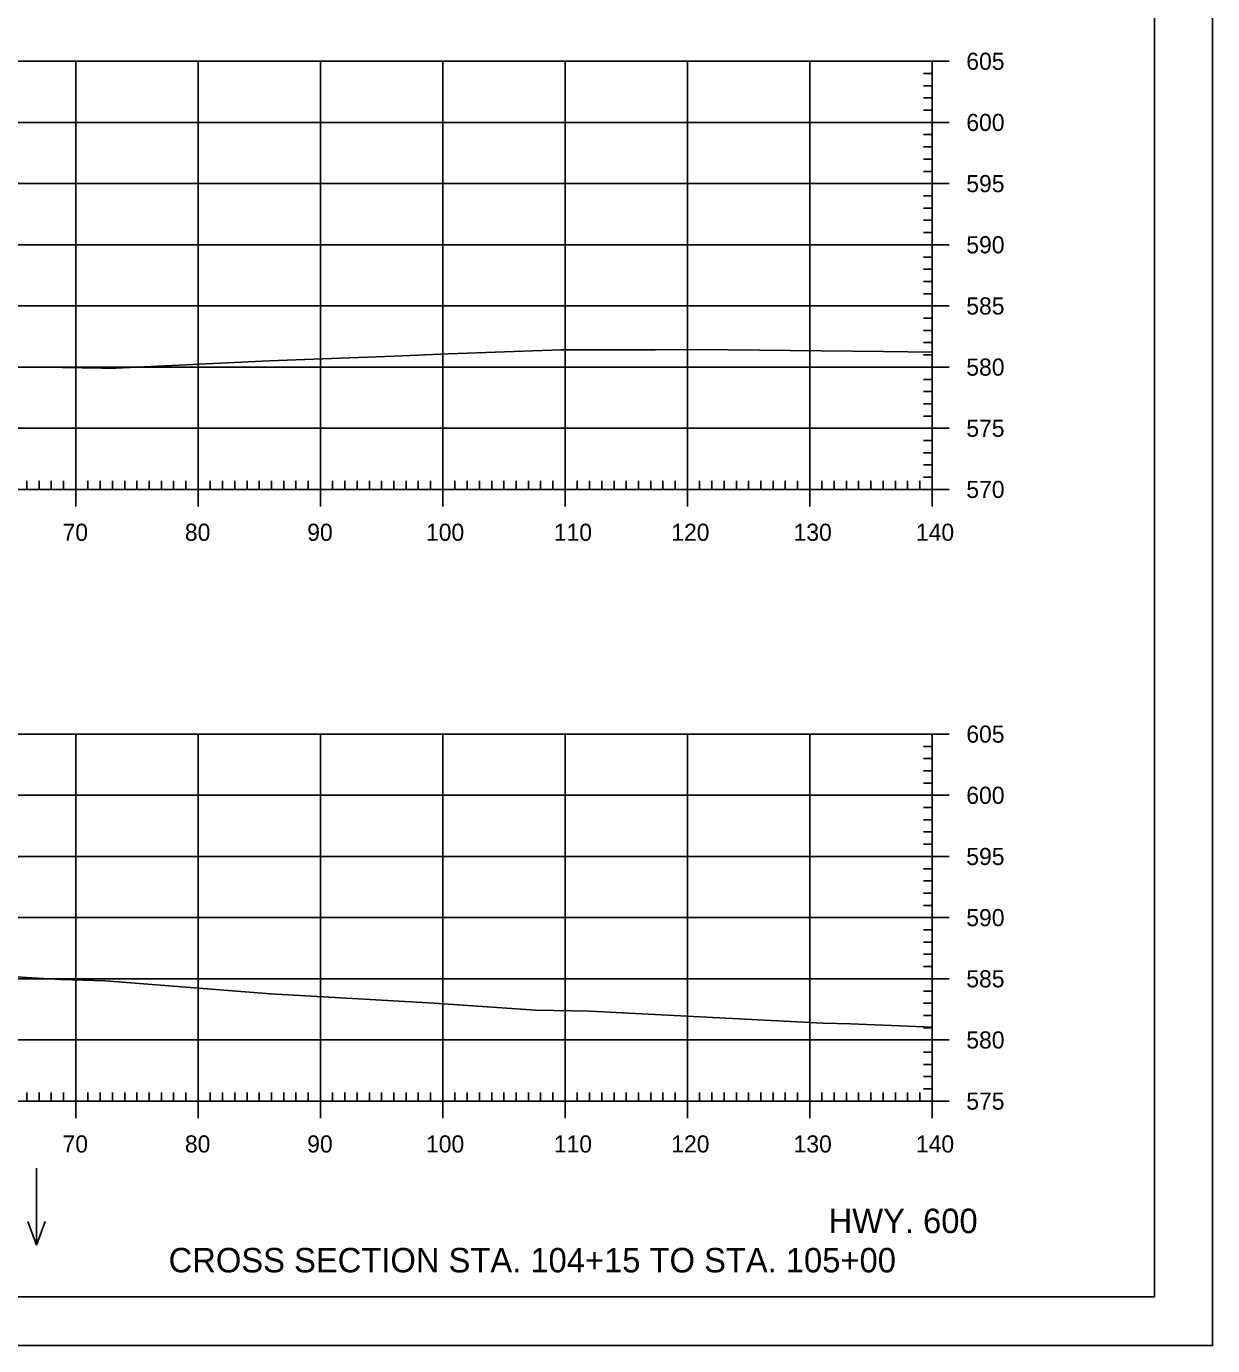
# Model space of a CAD drawing. Extents: x 961436 to 1372525, y 380079 to 2027791.
# Drawn here: x 1370699.8 to 1370796.7, y 380322.4 to 380430.3 of the extents above; entities that cross this region are included whole.
import ezdxf

# ---------------------------------------------------------------- set-up
doc = ezdxf.new("R2010")
doc.units = 0
for name, color, linetype in [('R_Axis', 7, 'Continuous'), ('R_Axis Annot', 7, 'Continuous'), ('R_Draft', 7, 'Continuous'), ('R_Exist Surface', 7, 'Continuous'), ('R_Grid', 7, 'Continuous'), ('R_No Plot', 7, 'Continuous'), ('R_Water Annot', 7, 'Continuous')]:
    doc.layers.add(name, color=color, linetype=linetype)

msp = doc.modelspace()

# ---------------------------------------------------------------- linework, layer by layer
at = {"layer": 'R_Axis'}
for p, q in [((1370775.21, 380427.4), (1370772.41, 380427.4)), ((1370773.81, 380392.4), (1370773.81, 380427.4)), ((1370773.81, 380426.4), (1370773.11, 380426.4)), ((1370773.81, 380425.4), (1370773.11, 380425.4)), ((1370773.81, 380424.4), (1370773.11, 380424.4)), ((1370773.81, 380423.4), (1370773.11, 380423.4)), ((1370775.21, 380422.4), (1370772.41, 380422.4)), ((1370773.81, 380421.4), (1370773.11, 380421.4)), ((1370773.81, 380420.4), (1370773.11, 380420.4)), ((1370773.81, 380419.4), (1370773.11, 380419.4)), ((1370773.81, 380418.4), (1370773.11, 380418.4)), ((1370775.21, 380417.4), (1370772.41, 380417.4)), ((1370773.81, 380416.4), (1370773.11, 380416.4)), ((1370773.81, 380415.4), (1370773.11, 380415.4)), ((1370773.81, 380414.4), (1370773.11, 380414.4)), ((1370773.81, 380413.4), (1370773.11, 380413.4)), ((1370775.21, 380412.4), (1370772.41, 380412.4)), ((1370773.81, 380411.4), (1370773.11, 380411.4)), ((1370773.81, 380410.4), (1370773.11, 380410.4)), ((1370773.81, 380409.4), (1370773.11, 380409.4)), ((1370773.81, 380408.4), (1370773.11, 380408.4)), ((1370775.21, 380407.4), (1370772.41, 380407.4)), ((1370773.81, 380406.4), (1370773.11, 380406.4)), ((1370773.81, 380405.4), (1370773.11, 380405.4)), ((1370773.81, 380404.4), (1370773.11, 380404.4)), ((1370773.81, 380403.4), (1370773.11, 380403.4)), ((1370775.21, 380402.4), (1370772.41, 380402.4)), ((1370773.81, 380401.4), (1370773.11, 380401.4)), ((1370773.81, 380400.4), (1370773.11, 380400.4)), ((1370773.81, 380399.4), (1370773.11, 380399.4)), ((1370773.81, 380398.4), (1370773.11, 380398.4)), ((1370775.21, 380397.4), (1370772.41, 380397.4)), ((1370773.81, 380396.4), (1370773.11, 380396.4)), ((1370773.81, 380395.4), (1370773.11, 380395.4)), ((1370703.81, 380391), (1370703.81, 380393.8)), ((1370713.81, 380391), (1370713.81, 380393.8)), ((1370723.81, 380391), (1370723.81, 380393.8)), ((1370733.81, 380391), (1370733.81, 380393.8)), ((1370743.81, 380391), (1370743.81, 380393.8)), ((1370753.81, 380391), (1370753.81, 380393.8)), ((1370763.81, 380391), (1370763.81, 380393.8)), ((1370773.81, 380394.4), (1370773.11, 380394.4)), ((1370773.81, 380391), (1370773.81, 380393.8)), ((1370699.81, 380392.4), (1370699.81, 380393.1)), ((1370700.81, 380392.4), (1370700.81, 380393.1)), ((1370701.81, 380392.4), (1370701.81, 380393.1)), ((1370702.81, 380392.4), (1370702.81, 380393.1)), ((1370704.81, 380392.4), (1370704.81, 380393.1)), ((1370705.81, 380392.4), (1370705.81, 380393.1)), ((1370706.81, 380392.4), (1370706.81, 380393.1)), ((1370707.81, 380392.4), (1370707.81, 380393.1)), ((1370708.81, 380392.4), (1370708.81, 380393.1)), ((1370709.81, 380392.4), (1370709.81, 380393.1)), ((1370710.81, 380392.4), (1370710.81, 380393.1)), ((1370711.81, 380392.4), (1370711.81, 380393.1)), ((1370712.81, 380392.4), (1370712.81, 380393.1)), ((1370714.81, 380392.4), (1370714.81, 380393.1)), ((1370715.81, 380392.4), (1370715.81, 380393.1)), ((1370716.81, 380392.4), (1370716.81, 380393.1)), ((1370717.81, 380392.4), (1370717.81, 380393.1)), ((1370718.81, 380392.4), (1370718.81, 380393.1)), ((1370719.81, 380392.4), (1370719.81, 380393.1)), ((1370720.81, 380392.4), (1370720.81, 380393.1)), ((1370721.81, 380392.4), (1370721.81, 380393.1)), ((1370722.81, 380392.4), (1370722.81, 380393.1)), ((1370724.81, 380392.4), (1370724.81, 380393.1)), ((1370725.81, 380392.4), (1370725.81, 380393.1)), ((1370726.81, 380392.4), (1370726.81, 380393.1)), ((1370727.81, 380392.4), (1370727.81, 380393.1)), ((1370728.81, 380392.4), (1370728.81, 380393.1)), ((1370729.81, 380392.4), (1370729.81, 380393.1)), ((1370730.81, 380392.4), (1370730.81, 380393.1)), ((1370731.81, 380392.4), (1370731.81, 380393.1)), ((1370732.81, 380392.4), (1370732.81, 380393.1)), ((1370734.81, 380392.4), (1370734.81, 380393.1)), ((1370735.81, 380392.4), (1370735.81, 380393.1)), ((1370736.81, 380392.4), (1370736.81, 380393.1)), ((1370737.81, 380392.4), (1370737.81, 380393.1)), ((1370738.81, 380392.4), (1370738.81, 380393.1)), ((1370739.81, 380392.4), (1370739.81, 380393.1)), ((1370740.81, 380392.4), (1370740.81, 380393.1)), ((1370741.81, 380392.4), (1370741.81, 380393.1)), ((1370742.81, 380392.4), (1370742.81, 380393.1)), ((1370744.81, 380392.4), (1370744.81, 380393.1)), ((1370745.81, 380392.4), (1370745.81, 380393.1)), ((1370746.81, 380392.4), (1370746.81, 380393.1)), ((1370747.81, 380392.4), (1370747.81, 380393.1)), ((1370748.81, 380392.4), (1370748.81, 380393.1)), ((1370749.81, 380392.4), (1370749.81, 380393.1)), ((1370750.81, 380392.4), (1370750.81, 380393.1)), ((1370751.81, 380392.4), (1370751.81, 380393.1)), ((1370752.81, 380392.4), (1370752.81, 380393.1)), ((1370754.81, 380392.4), (1370754.81, 380393.1)), ((1370755.81, 380392.4), (1370755.81, 380393.1)), ((1370756.81, 380392.4), (1370756.81, 380393.1)), ((1370757.81, 380392.4), (1370757.81, 380393.1)), ((1370758.81, 380392.4), (1370758.81, 380393.1)), ((1370759.81, 380392.4), (1370759.81, 380393.1)), ((1370760.81, 380392.4), (1370760.81, 380393.1)), ((1370761.81, 380392.4), (1370761.81, 380393.1)), ((1370762.81, 380392.4), (1370762.81, 380393.1)), ((1370764.81, 380392.4), (1370764.81, 380393.1)), ((1370765.81, 380392.4), (1370765.81, 380393.1)), ((1370766.81, 380392.4), (1370766.81, 380393.1)), ((1370767.81, 380392.4), (1370767.81, 380393.1)), ((1370768.81, 380392.4), (1370768.81, 380393.1)), ((1370769.81, 380392.4), (1370769.81, 380393.1)), ((1370770.81, 380392.4), (1370770.81, 380393.1)), ((1370771.81, 380392.4), (1370771.81, 380393.1)), ((1370772.81, 380392.4), (1370772.81, 380393.1)), ((1370773.81, 380393.4), (1370773.11, 380393.4)), ((1370493.81, 380392.4), (1370773.81, 380392.4)), ((1370775.21, 380392.4), (1370772.41, 380392.4)), ((1370775.21, 380372.4), (1370772.41, 380372.4)), ((1370773.81, 380342.4), (1370773.81, 380372.4)), ((1370773.81, 380371.4), (1370773.11, 380371.4)), ((1370773.81, 380370.4), (1370773.11, 380370.4)), ((1370773.81, 380369.4), (1370773.11, 380369.4)), ((1370773.81, 380368.4), (1370773.11, 380368.4)), ((1370775.21, 380367.4), (1370772.41, 380367.4)), ((1370773.81, 380366.4), (1370773.11, 380366.4)), ((1370773.81, 380365.4), (1370773.11, 380365.4)), ((1370773.81, 380364.4), (1370773.11, 380364.4)), ((1370773.81, 380363.4), (1370773.11, 380363.4)), ((1370775.21, 380362.4), (1370772.41, 380362.4)), ((1370773.81, 380361.4), (1370773.11, 380361.4)), ((1370773.81, 380360.4), (1370773.11, 380360.4)), ((1370773.81, 380359.4), (1370773.11, 380359.4)), ((1370773.81, 380358.4), (1370773.11, 380358.4)), ((1370775.21, 380357.4), (1370772.41, 380357.4)), ((1370773.81, 380356.4), (1370773.11, 380356.4)), ((1370773.81, 380355.4), (1370773.11, 380355.4)), ((1370773.81, 380354.4), (1370773.11, 380354.4)), ((1370773.81, 380353.4), (1370773.11, 380353.4)), ((1370775.21, 380352.4), (1370772.41, 380352.4)), ((1370773.81, 380351.4), (1370773.11, 380351.4)), ((1370773.81, 380350.4), (1370773.11, 380350.4)), ((1370773.81, 380349.4), (1370773.11, 380349.4)), ((1370773.81, 380348.4), (1370773.11, 380348.4)), ((1370775.21, 380347.4), (1370772.41, 380347.4)), ((1370773.81, 380346.4), (1370773.11, 380346.4)), ((1370773.81, 380345.4), (1370773.11, 380345.4)), ((1370773.81, 380344.4), (1370773.11, 380344.4)), ((1370699.81, 380342.4), (1370699.81, 380343.1)), ((1370700.81, 380342.4), (1370700.81, 380343.1)), ((1370701.81, 380342.4), (1370701.81, 380343.1)), ((1370702.81, 380342.4), (1370702.81, 380343.1)), ((1370703.81, 380341), (1370703.81, 380343.8)), ((1370704.81, 380342.4), (1370704.81, 380343.1)), ((1370705.81, 380342.4), (1370705.81, 380343.1)), ((1370706.81, 380342.4), (1370706.81, 380343.1)), ((1370707.81, 380342.4), (1370707.81, 380343.1)), ((1370708.81, 380342.4), (1370708.81, 380343.1)), ((1370709.81, 380342.4), (1370709.81, 380343.1)), ((1370710.81, 380342.4), (1370710.81, 380343.1)), ((1370711.81, 380342.4), (1370711.81, 380343.1)), ((1370712.81, 380342.4), (1370712.81, 380343.1)), ((1370713.81, 380341), (1370713.81, 380343.8)), ((1370714.81, 380342.4), (1370714.81, 380343.1)), ((1370715.81, 380342.4), (1370715.81, 380343.1)), ((1370716.81, 380342.4), (1370716.81, 380343.1)), ((1370717.81, 380342.4), (1370717.81, 380343.1)), ((1370718.81, 380342.4), (1370718.81, 380343.1)), ((1370719.81, 380342.4), (1370719.81, 380343.1)), ((1370720.81, 380342.4), (1370720.81, 380343.1)), ((1370721.81, 380342.4), (1370721.81, 380343.1)), ((1370722.81, 380342.4), (1370722.81, 380343.1)), ((1370723.81, 380341), (1370723.81, 380343.8)), ((1370724.81, 380342.4), (1370724.81, 380343.1)), ((1370725.81, 380342.4), (1370725.81, 380343.1)), ((1370726.81, 380342.4), (1370726.81, 380343.1)), ((1370727.81, 380342.4), (1370727.81, 380343.1)), ((1370728.81, 380342.4), (1370728.81, 380343.1)), ((1370729.81, 380342.4), (1370729.81, 380343.1)), ((1370730.81, 380342.4), (1370730.81, 380343.1)), ((1370731.81, 380342.4), (1370731.81, 380343.1)), ((1370732.81, 380342.4), (1370732.81, 380343.1)), ((1370733.81, 380341), (1370733.81, 380343.8)), ((1370734.81, 380342.4), (1370734.81, 380343.1)), ((1370735.81, 380342.4), (1370735.81, 380343.1)), ((1370736.81, 380342.4), (1370736.81, 380343.1)), ((1370737.81, 380342.4), (1370737.81, 380343.1)), ((1370738.81, 380342.4), (1370738.81, 380343.1)), ((1370739.81, 380342.4), (1370739.81, 380343.1)), ((1370740.81, 380342.4), (1370740.81, 380343.1)), ((1370741.81, 380342.4), (1370741.81, 380343.1)), ((1370742.81, 380342.4), (1370742.81, 380343.1)), ((1370743.81, 380341), (1370743.81, 380343.8)), ((1370744.81, 380342.4), (1370744.81, 380343.1)), ((1370745.81, 380342.4), (1370745.81, 380343.1)), ((1370746.81, 380342.4), (1370746.81, 380343.1)), ((1370747.81, 380342.4), (1370747.81, 380343.1)), ((1370748.81, 380342.4), (1370748.81, 380343.1)), ((1370749.81, 380342.4), (1370749.81, 380343.1)), ((1370750.81, 380342.4), (1370750.81, 380343.1)), ((1370751.81, 380342.4), (1370751.81, 380343.1)), ((1370752.81, 380342.4), (1370752.81, 380343.1)), ((1370753.81, 380341), (1370753.81, 380343.8)), ((1370754.81, 380342.4), (1370754.81, 380343.1)), ((1370755.81, 380342.4), (1370755.81, 380343.1)), ((1370756.81, 380342.4), (1370756.81, 380343.1)), ((1370757.81, 380342.4), (1370757.81, 380343.1)), ((1370758.81, 380342.4), (1370758.81, 380343.1)), ((1370759.81, 380342.4), (1370759.81, 380343.1)), ((1370760.81, 380342.4), (1370760.81, 380343.1)), ((1370761.81, 380342.4), (1370761.81, 380343.1)), ((1370762.81, 380342.4), (1370762.81, 380343.1)), ((1370763.81, 380341), (1370763.81, 380343.8)), ((1370764.81, 380342.4), (1370764.81, 380343.1)), ((1370765.81, 380342.4), (1370765.81, 380343.1)), ((1370766.81, 380342.4), (1370766.81, 380343.1)), ((1370767.81, 380342.4), (1370767.81, 380343.1)), ((1370768.81, 380342.4), (1370768.81, 380343.1)), ((1370769.81, 380342.4), (1370769.81, 380343.1)), ((1370770.81, 380342.4), (1370770.81, 380343.1)), ((1370771.81, 380342.4), (1370771.81, 380343.1)), ((1370772.81, 380342.4), (1370772.81, 380343.1)), ((1370773.81, 380343.4), (1370773.11, 380343.4)), ((1370773.81, 380341), (1370773.81, 380343.8)), ((1370493.81, 380342.4), (1370773.81, 380342.4)), ((1370775.21, 380342.4), (1370772.41, 380342.4))]:
    msp.add_line(p, q, dxfattribs=at)
at = {"layer": 'R_Exist Surface'}
for points in [[(1370696.26, 380402.45), (1370701.11, 380402.39), (1370705.94, 380402.32), (1370707.12, 380402.32), (1370719.63, 380402.91), (1370729.83, 380403.29), (1370734.27, 380403.48), (1370743.45, 380403.8), (1370750.14, 380403.82), (1370750.33, 380403.82), (1370751.18, 380403.81), (1370754.59, 380403.83), (1370769.84, 380403.67), (1370773.81, 380403.62)], [(1370688.34, 380353.25), (1370700.21, 380352.47), (1370702.58, 380352.35), (1370706.24, 380352.24), (1370719.74, 380351.16), (1370733.11, 380350.42), (1370741.38, 380349.83), (1370745.86, 380349.74), (1370764.88, 380348.78), (1370767.15, 380348.72), (1370773.81, 380348.45)]]:
    msp.add_lwpolyline(points, dxfattribs=at)
at = {"layer": 'R_Grid'}
for p, q in [((1370493.81, 380427.4), (1370773.81, 380427.4)), ((1370703.81, 380392.4), (1370703.81, 380427.4)), ((1370713.81, 380392.4), (1370713.81, 380427.4)), ((1370723.81, 380392.4), (1370723.81, 380427.4)), ((1370733.81, 380392.4), (1370733.81, 380427.4)), ((1370743.81, 380392.4), (1370743.81, 380427.4)), ((1370753.81, 380392.4), (1370753.81, 380427.4)), ((1370763.81, 380392.4), (1370763.81, 380427.4)), ((1370773.81, 380392.4), (1370773.81, 380427.4)), ((1370493.81, 380422.4), (1370773.81, 380422.4)), ((1370493.81, 380417.4), (1370773.81, 380417.4)), ((1370493.81, 380412.4), (1370773.81, 380412.4)), ((1370493.81, 380407.4), (1370773.81, 380407.4)), ((1370493.81, 380402.4), (1370773.81, 380402.4)), ((1370493.81, 380397.4), (1370773.81, 380397.4)), ((1370493.81, 380392.4), (1370773.81, 380392.4)), ((1370493.81, 380372.4), (1370773.81, 380372.4)), ((1370703.81, 380342.4), (1370703.81, 380372.4)), ((1370713.81, 380342.4), (1370713.81, 380372.4)), ((1370723.81, 380342.4), (1370723.81, 380372.4)), ((1370733.81, 380342.4), (1370733.81, 380372.4)), ((1370743.81, 380342.4), (1370743.81, 380372.4)), ((1370753.81, 380342.4), (1370753.81, 380372.4)), ((1370763.81, 380342.4), (1370763.81, 380372.4)), ((1370773.81, 380342.4), (1370773.81, 380372.4)), ((1370493.81, 380367.4), (1370773.81, 380367.4)), ((1370493.81, 380362.4), (1370773.81, 380362.4)), ((1370493.81, 380357.4), (1370773.81, 380357.4)), ((1370493.81, 380352.4), (1370773.81, 380352.4)), ((1370493.81, 380347.4), (1370773.81, 380347.4)), ((1370493.81, 380342.4), (1370773.81, 380342.4))]:
    msp.add_line(p, q, dxfattribs=at)
at = {"layer": 'R_No Plot'}
for p, q in [((1370791.99, 380326.4), (1370791.99, 380531.86)), ((1370791.99, 380326.4), (1370475.81, 380326.4)), ((1370463.41, 380322.42), (1370796.74, 380322.42))]:
    msp.add_line(p, q, dxfattribs=at)
for points in [[(1370463.4, 380535.75), (1370796.74, 380535.75), (1370796.74, 380322.41), (1370463.4, 380322.41)], [(1370709.73, 380531.86), (1370729.35, 380531.86), (1370729.35, 380521.98), (1370745.46, 380521.98), (1370768.66, 380521.98), (1370768.78, 380493.82), (1370791.99, 380493.82), (1370791.99, 380326.4), (1370475.81, 380326.4), (1370475.81, 380531.86)]]:
    msp.add_lwpolyline(points, close=True, dxfattribs=at)
at = {"layer": 'R_Water Annot'}
for p, q in [((1370700.6, 380336.91), (1370700.6, 380330.62)), ((1370700.6, 380330.62), (1370699.9, 380332.55)), ((1370700.6, 380330.62), (1370701.3, 380332.55))]:
    msp.add_line(p, q, dxfattribs=at)

# ---------------------------------------------------------------- texts
at = {"layer": 'R_Axis Annot'}
for s, p in [('605', (1370776.61, 380426.7)), ('600', (1370776.61, 380421.7)), ('595', (1370776.61, 380416.7)), ('590', (1370776.61, 380411.7)), ('585', (1370776.61, 380406.7)), ('580', (1370776.61, 380401.7)), ('575', (1370776.61, 380396.7)), ('570', (1370776.61, 380391.7)), ('70', (1370702.73, 380388.2)), ('80', (1370712.73, 380388.2)), ('90', (1370722.73, 380388.2)), ('100', (1370732.44, 380388.2)), ('110', (1370742.89, 380388.2)), ('120', (1370752.49, 380388.2)), ('130', (1370762.49, 380388.2)), ('140', (1370772.49, 380388.2)), ('605', (1370776.61, 380371.7)), ('600', (1370776.61, 380366.7)), ('595', (1370776.61, 380361.7)), ('590', (1370776.61, 380356.7)), ('585', (1370776.61, 380351.7)), ('580', (1370776.61, 380346.7)), ('575', (1370776.61, 380341.7)), ('70', (1370702.73, 380338.2)), ('80', (1370712.73, 380338.2)), ('90', (1370722.73, 380338.2)), ('100', (1370732.44, 380338.2)), ('110', (1370742.89, 380338.2)), ('120', (1370752.49, 380338.2)), ('130', (1370762.49, 380338.2)), ('140', (1370772.49, 380338.2))]:
    msp.add_text(s, height=1.4, dxfattribs=at).set_placement(p)
at = {"layer": 'R_Draft'}
for s, p in [('HWY. 600', (1370765.35, 380331.61)), ('CROSS SECTION STA. 104+15 TO STA. 105+00', (1370711.4, 380328.4))]:
    msp.add_text(s, height=2, dxfattribs=at).set_placement(p)

doc.saveas('drawing.dxf')
